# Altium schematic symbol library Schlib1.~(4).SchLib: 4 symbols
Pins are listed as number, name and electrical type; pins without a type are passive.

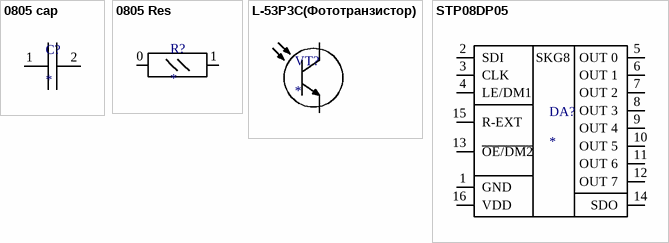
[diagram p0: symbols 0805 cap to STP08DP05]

## 0805 cap
designator С?
pins: 1, 2

## 0805 Res
designator R?
pins: 0, 1

## L-53P3C(Фототранзистор)
designator VT?

## STP08DP05
designator DA?
pins: 1 GND, 2 SDI, 3 CLK, 4 LE/DM1, 5 OUT 0, 6 OUT 1, 7 OUT 2, 8 OUT 3, 9 OUT 4, 10 OUT 5, 11 OUT 6, 12 OUT 7, 13 ~{OE/DM2}, 14 SDO, 15 R-EXT, 16 VDD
